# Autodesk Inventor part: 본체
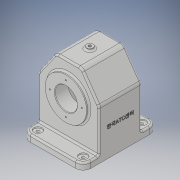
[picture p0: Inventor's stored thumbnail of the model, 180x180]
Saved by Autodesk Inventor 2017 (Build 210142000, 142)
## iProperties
Part Number: 본체
Material: 일반
Document SubType Name: Modeling
Designer: MRC
Density: 1 g/cm^3
Appearance: 기본값
Author: MRC
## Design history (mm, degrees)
sketch "스케치1"
  geometry: L1 (-55, -65)-(-55, 12); L2 (-55, 12)-(-23.491, 57); L3 (-23.491, 57)-(23.491, 57); L4 (23.491, 57)-(55, 12); L5 (55, 12)-(55, -65); L6 (55, -65)-(-55, -65); 3 further points
  constraints: 12 end point, 2 midpoint, 2 vertical, 2 vertical alignment, 1 horizontal alignment, 1 parallel, 1 perpendicular
  dimensions: "d0" = 65 distance from line of L6 point (0, 0); "d1" = 77 distance of L1.start L1.end; "d3" = 122 distance between parallel lines of L6 L3; "d4" = 110 distance between parallel lines of L5 L1; "d5" = 35 deg angle of L1 L2
extrude "돌출1" new body sketch "스케치1" stored distance "d6" = 77; taper "d7" = 0 deg
feature "쉘1" dims "d8" = 5
sketch "스케치4"
  geometry: C1 r 37.5 at (0, 0); 1 further point
  constraints: 1 centre point, 1 coincident
  dimensions: "d15" = 75 diameter of C1
extrude "돌출3" join sketch "스케치4" distance "d16" = 5; taper "d17" = 0 deg
sketch "스케치5"
  geometry: C1 r 31 at (0, 0); 1 further point
  constraints: 1 centre point, 1 coincident
  dimensions: "d18" = 62 diameter of C1
extrude "돌출4" join sketch "스케치5" distance "d19" = 10; taper "d20" = 0 deg
sketch "스케치7"
  geometry: L1 (0, 0)-(110, 0) reference; L2 (110, 0)-(110, 28.5); L3 (110, 28.5)-(0, 28.5); L4 (0, 28.5)-(0, 0); L5 (105, -72)-(5, -72) reference; L6 (5, -72)-(5, -5) reference; L7 (5, -5)-(105, -5) reference; L8 (105, -5)-(105, -72) reference; L9 (110, 0)-(110, -77) reference; L10 (0, 0)-(110, 0) reference; L11 (0, -77)-(0, 0) reference; L12 (110, -77)-(0, -77) reference; 1 further point
  constraints: 6 end point, 2 perpendicular, 1 vertical
  dimensions: "d21" = 67 distance from line of L3 point (55, -38.5)
extrude "돌출5" join sketch "스케치7" distance "d22" = 12; taper "d23" = 0 deg
node "작업 평면1"
sketch "스케치9"
  geometry: C1 r 27 at (0, 0); 1 further point
  constraints: 1 centre point, 1 coincident
  dimensions: "d25" = 54 diameter of C1
extrude "돌출6" join sketch "스케치9" stored distance "d26" = 12; taper "d27" = 45 deg
hole "구멍1" diameter "d30" = 40; stored, may be unused: countersink angle "d34" = 90 deg, drill point angle "d36" = 0 deg; dims "d28" = 10, "d29" = 10, "d31" = 6, "d32" = 4, "d33" = 2, "d35" = 50
hole "구멍2" diameter "d39" = 40; stored, may be unused: countersink angle "d43" = 90 deg, drill point angle "d45" = 0 deg; dims "d37" = 10, "d38" = 10, "d40" = 6, "d41" = 4, "d42" = 2, "d44" = 15
node "작업 평면2"
sketch "스케치11"
  geometry: C1 r 6 at (0, 0); 1 further point
  constraints: 1 centre point, 1 coincident
  dimensions: "d47" = 12 diameter of C1
extrude "돌출7" join sketch "스케치11" stored distance "d48" = 12; taper "d49" = 0 deg
sketch "스케치12"
  geometry: A1 r 29 centre (0, 0) between (0, 29) and (29, 0); 3 further points
  constraints: 4 point on circle, 2 horizontal alignment, 2 vertical alignment, 1 centre point, 1 coincident
  dimensions: "d50" = 58 diameter of A1
hole "구멍3" sketch "스케치12" at (0, 29), (29, 0), (-29, 0), (0, -29) diameter "d51" = 2.459; stored, may be unused: countersink angle "d55" = 90 deg, drill point angle "d57" = 118 deg; dims "d52" = 6, "d53" = 4, "d54" = 2, "d56" = 8
sketch "스케치13"
  geometry: A1 r 26 centre (0, 0) between (0, 26) and (26, 0); 3 further points
  constraints: 4 point on circle, 2 horizontal alignment, 2 vertical alignment, 1 centre point, 1 coincident
  dimensions: "d58" = 52 diameter of A1
hole "구멍4" sketch "스케치13" at (0, 26), (26, 0), (0, -26), (-26, 0) diameter "d59" = 2.459; stored, may be unused: countersink angle "d63" = 90 deg, drill point angle "d65" = 118 deg; dims "d60" = 6, "d61" = 4, "d62" = 2, "d64" = 8
hole "구멍5" diameter "d68" = 5.188; stored, may be unused: countersink angle "d72" = 90 deg, drill point angle "d74" = 118 deg; dims "d66" = 10, "d67" = 10, "d69" = 30, "d70" = 4, "d71" = 2, "d73" = 30
fillet "모깎기1" dims "d75" = 14
sketch "스케치14"
  geometry: A1 r 14 centre (14, -91.5) between (0, -91.5) and (14, -105.5) reference; A2 r 14 centre (96, -91.5) between (96, -105.5) and (110, -91.5) reference; A3 r 14 centre (96, 14.5) between (110, 14.5) and (96, 28.5) reference; A4 r 14 centre (14, 14.5) between (14, 28.5) and (0, 14.5) reference; 5 further points
  constraints: 4 coincident
hole "구멍6" sketch "스케치14" at (14, -91.5), (96, -91.5), (96, 14.5), (14, 14.5) diameter "d76" = 5.5; stored, may be unused: countersink angle "d80" = 90 deg, drill point angle "d82" = 118 deg; dims "d77" = 6, "d78" = 15, "d79" = 2, "d81" = 12
node "작업 평면3"
sketch "스케치15"
  geometry: L1 (-77, 53)-(-77, -53) reference; L2 (-65, 38.5)-(12, 38.5) reference; 2 further points
  constraints: 1 other
  dimensions: "d84" = 50 distance from line of point (-27, 0) L1; "d85" = 38.5 distance from line of L2 point (-27, 0)
feature "엠보싱1" sketch "스케치15" dims "d0" = 65, "d1" = 77, "d3" = 122, "d4" = 110, "d5" = 35 deg, "d86" = 0.5, "d87" = 0
fillet "모깎기2" dims "d88" = 10
fillet "모깎기3" dims "d89" = 3
fillet "모깎기4" dims "d90" = 3
fillet "모깎기5" dims "d91" = 3
chamfer "모따기1" distance "d92" = 1; stored, may be unused: second distance "d93" = 2, angle "d94" = 45 deg
node "솔리드1"
mirror "미러1"
node "투영된 루프1"
other parameters: "d24" = -24, "d46" = 61, "d83" = 115.5
